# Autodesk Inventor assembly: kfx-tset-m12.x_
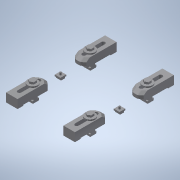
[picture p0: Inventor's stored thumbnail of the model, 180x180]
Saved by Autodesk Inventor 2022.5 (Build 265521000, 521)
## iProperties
Created: 2021-10
Part Number: kfx-tset-m12.x_
Material: 一般
Document SubType Name: Assembly
Designer: ImaoCorp
Sending System: SOLIDWORKS 2019-2019304
MC: AMD64
MC_MODEL: Intel64 Family 6 Model 60 Stepping 3, GenuineIntel
OS: Windows_NT
FRU: Parasolid Version 31.0, build 290,  9- 1-2019
FORMAT: text
GUISE: transmit
KEY: kfx-tset-m12
FILE: kfx-tset-m12.x_t
DATE: Thu Oct 14 10:02:48 2021
Author: ImaoCorp
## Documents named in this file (15)
- X:\14_SW2022-Inv2022\00_全2023-1023新製品(TCC)まで\k\kfx-tset-m12\KFX-TSET-M12.iam
- X:\14_SW2022-Inv2022\00_全2023-1023新製品(TCC)まで\k\kfx-tset-m12\kfx-tset-m12_01.ipt
- X:\14_SW2022-Inv2022\00_全2023-1023新製品(TCC)まで\k\kfx-tset-m12\kfx-tset-m12_02.ipt
- X:\14_SW2022-Inv2022\00_全2023-1023新製品(TCC)まで\k\kfx-tset-m12\kfx-tset-m12_03.ipt
- X:\14_SW2022-Inv2022\00_全2023-1023新製品(TCC)まで\k\kfx-tset-m12\kfx-tset-m12_04.ipt
- X:\14_SW2022-Inv2022\00_全2023-1023新製品(TCC)まで\k\kfx-tset-m12\kfx-tset-m12_05.ipt
- X:\14_SW2022-Inv2022\00_全2023-1023新製品(TCC)まで\k\kfx-tset-m12\kfx-tset-m12_06.ipt
- X:\14_SW2022-Inv2022\00_全2023-1023新製品(TCC)まで\k\kfx-tset-m12\kfx-tset-m12_07.ipt
- X:\14_SW2022-Inv2022\00_全2023-1023新製品(TCC)まで\k\kfx-tset-m12\kfx-tset-m12_08.ipt
- X:\14_SW2022-Inv2022\00_全2023-1023新製品(TCC)まで\k\kfx-tset-m12\kfx-tset-m12_09.ipt
- X:\14_SW2022-Inv2022\00_全2023-1023新製品(TCC)まで\k\kfx-tset-m12\kfx-tset-m12_10.ipt
- X:\14_SW2022-Inv2022\00_全2023-1023新製品(TCC)まで\k\kfx-tset-m12\kfx-tset-m12_11.ipt
- X:\14_SW2022-Inv2022\00_全2023-1023新製品(TCC)まで\k\kfx-tset-m12\kfx-tset-m12_12.ipt
- X:\14_SW2022-Inv2022\00_全2023-1023新製品(TCC)まで\k\kfx-tset-m12\kfx-tset-m12_13.ipt
- X:\14_SW2022-Inv2022\00_全2023-1023新製品(TCC)まで\k\kfx-tset-m12\kfx-tset-m12_14.ipt
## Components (14 placed, 14 different names)
1. kfx-tset-m12_01
2. kfx-tset-m12_02
3. kfx-tset-m12_03
4. kfx-tset-m12_04
5. kfx-tset-m12_05
6. kfx-tset-m12_06
7. kfx-tset-m12_07
8. kfx-tset-m12_08
9. kfx-tset-m12_09
10. kfx-tset-m12_10
11. kfx-tset-m12_11
12. kfx-tset-m12_12
13. kfx-tset-m12_13
14. kfx-tset-m12_14
